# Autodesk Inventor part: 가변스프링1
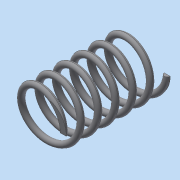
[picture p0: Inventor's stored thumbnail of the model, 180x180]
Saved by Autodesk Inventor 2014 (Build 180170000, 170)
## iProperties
Created: 2023-01
Part Number: 가변스프링1
Material: 스테인레스 스틸
Document SubType Name: Modeling
Designer: dg
Density: 8.08 g/cm^3
Appearance: 반연마
Mass: 7.99982 g
Surface Area: 20.0872 cm^2
Volume: 0.990077 cm^3
Author: dg
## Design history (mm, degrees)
sketch "스케치1"
  geometry: L1 (8.5, 0)-(0, 0); L2 (0, 0)-(0, 26.33); L3 (0, 26.33)-(8.5, 26.33); C1 r 1 at (8.5, 0)
  constraints: 6 end point, 1 centre point, 1 coincident, 1 horizontal, 1 parallel, 1 vertical, 1 vertical alignment
  dimensions: "d0" = 2 diameter of C1; "d1" = 26.33013 distance of L1.end L2.end (derived); "d2" = 17 diameter of L1.start L2
feature "코일1" sketch "스케치1" pitch "d3" = 10; turns "d5" = 6; dims "d4" = 26.33013 (= d1), "d6" = 0, angle "d7" = 90 deg, angle "d8" = 90 deg, "d9" = 0, "d10" = 0
node "작업 평면1"
node "작업 평면2"
feature "분할1"
feature "분할2"
node "솔리드1"
other parameters: "d11" = 90 deg, "d12" = 90 deg
